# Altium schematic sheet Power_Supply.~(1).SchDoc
size A4
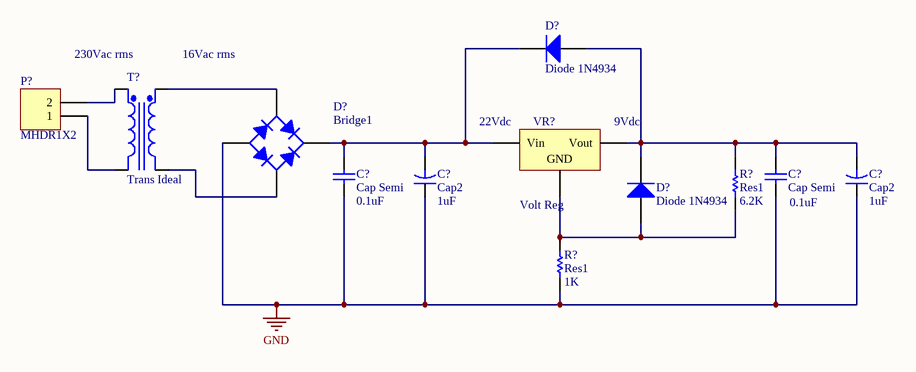
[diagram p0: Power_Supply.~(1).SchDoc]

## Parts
(Parts that share a designator on the sheet are numbered #1, #2 ... from top to bottom, then left to right.)
C?#1  Cap Semi  value 0.1uF  [C1206]
C?#2  Cap2  value 1uF  [CAPR5-4X5]
C?#3  Cap Semi  value 0.1uF  [C1206]
C?#4  Cap2  value 1uF  [CAPR5-4X5]
D?#1  Diode 1N4934  [DO-41]
D?#2  Bridge1  [D-38]
D?#3  Diode 1N4934  [DO-41]
P?  MHDR1X2  [MHDR1X2]
R?#1  Res1  value 6.2K  [AXIAL-0.3]
R?#2  Res1  value 1K  [AXIAL-0.3]
T?  Trans Ideal  [TRF_4]
VR?  Volt Reg  [D2PAK_N]

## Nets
GND: C?#1.1 C?#2.1 C?#3.1 C?#4.1 D?#2.3(A) R?#2.1
NetC?#1_2: C?#1.2 C?#2.2 D?#1.2(K) D?#2.1(K) VR?.1(Vin)
NetC?#3_2: C?#3.2 C?#4.2 D?#1.1(A) D?#3.2(K) R?#1.1 VR?.3(Vout)
NetD?#2_2: D?#2.2(C) T?.4(Sec-)
NetD?#2_4: D?#2.4(C) T?.3(Sec+)
NetD?#3_1: D?#3.1(A) R?#1.2 R?#2.2 VR?.2(GND)
NetP?_1: P?.1 T?.2(Pri-)
NetP?_2: P?.2 T?.1(Pri+)

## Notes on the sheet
- 230Vac rms
- 16Vac rms
- (near VR?) 22Vdc
- (near VR?) 9Vdc

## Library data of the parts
C?#1 C?#3 = Cap Semi: Capacitor (Semiconductor SIM Model)
C?#2 C?#4 = Cap2: Capacitor
D?#1 D?#3 = Diode 1N4934: 1 Amp Fast Recovery Rectifier
D?#2 = Bridge1: Full Wave Diode Bridge
P? = MHDR1X2: Header, 2-Pin
R?#1 R?#2 = Res1: Resistor
T? = Trans Ideal: Transformer (Ideal)
VR? = Volt Reg: Voltage Regulator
